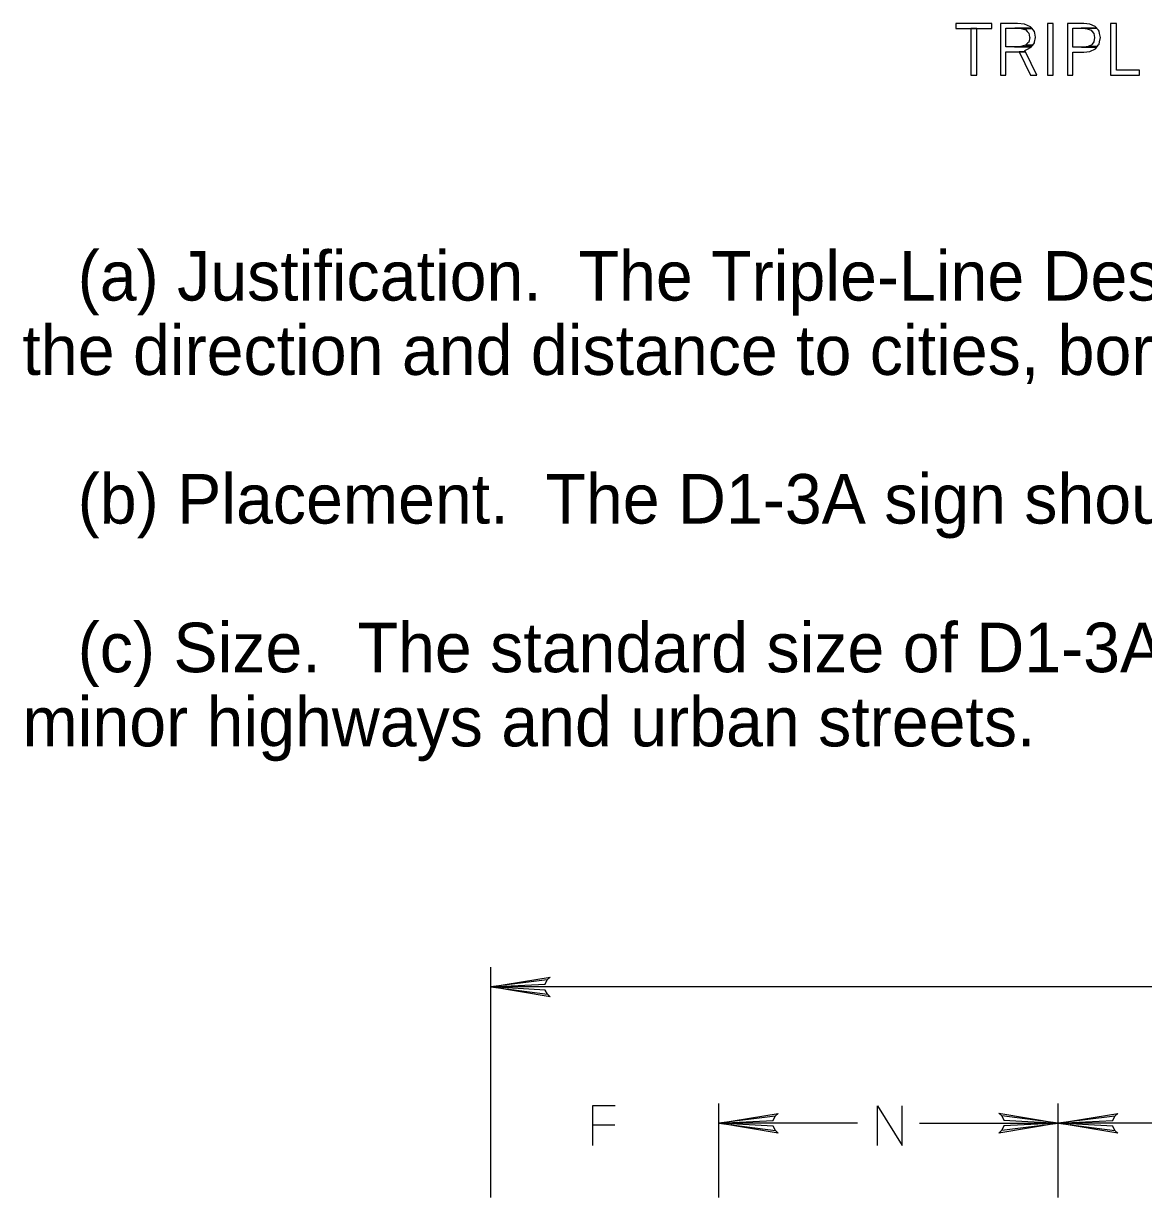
# Model space of a CAD drawing. Extents: x 0.011 to 0.188, y 0.004 to 0.261.
# Drawn here: x 0.0252 to 0.0822, y 0.1928 to 0.2525 of the extents above; entities that cross this region are included whole.
import ezdxf

# ---------------------------------------------------------------- set-up
doc = ezdxf.new("R2010")
doc.units = 0
doc.layers.add('1', color=7, linetype='Continuous')
doc.layers.add('3', color=7, linetype='Continuous')

# ---------------------------------------------------------------- blocks, each defined once
blk = doc.blocks.new('RARROW')
at = {"layer": '3'}
for p, q in [((-2.156, 0.285), (-2.2665, 0.384625)), ((-2.2665, 0.384625), (0, 0)), ((0, 0), (-2.2665, -0.379125)), ((-2.156, 0.285), (-2.075625, 0.12075)), ((0, 0), (-2.156, 0.285)), ((-2.14975, -0.2705), (0, 0)), ((-2.075625, 0.12075), (0, 0)), ((0, 0), (-2.074, -0.108)), ((-2.2665, -0.379125), (-2.14975, -0.2705)), ((-2.074, -0.108), (-2.14975, -0.2705))]:
    blk.add_line(p, q, dxfattribs=at)

msp = doc.modelspace()

# ---------------------------------------------------------------- linework, layer by layer
at = {"layer": '1'}
for points in [[(0.072644, 0.252474), (0.072644, 0.252222), (0.074473, 0.252222), (0.074473, 0.252474)], [(0.073409, 0.252222), (0.073409, 0.249848), (0.073707, 0.249848), (0.073707, 0.252222)], [(0.074907, 0.251038), (0.074907, 0.249848), (0.075193, 0.249848), (0.075193, 0.251038), (0.076181, 0.251038), (0.076147, 0.251107), (0.07626, 0.251146), (0.076466, 0.251262), (0.076481, 0.251282), (0.075193, 0.251282), (0.075193, 0.251286), (0.075193, 0.251303), (0.075193, 0.251377), (0.075193, 0.251483), (0.075193, 0.251531), (0.075193, 0.251755), (0.075193, 0.251778), (0.075193, 0.251988), (0.075193, 0.252073), (0.075193, 0.252149), (0.075193, 0.252214), (0.075193, 0.252227), (0.075193, 0.252229), (0.076505, 0.252229), (0.076439, 0.252309), (0.076135, 0.25244), (0.075787, 0.25247), (0.075645, 0.252474), (0.074907, 0.252474), (0.074907, 0.25247), (0.074907, 0.25244), (0.074907, 0.252309), (0.074907, 0.252229), (0.074907, 0.252227), (0.074907, 0.252214), (0.074907, 0.252149), (0.074907, 0.252073), (0.074907, 0.251988), (0.074907, 0.251778), (0.074907, 0.251755), (0.074907, 0.251531), (0.074907, 0.251483), (0.074907, 0.251377), (0.074907, 0.251303), (0.074907, 0.251286), (0.074907, 0.251282), (0.074907, 0.251262), (0.074907, 0.251146), (0.074907, 0.251107)], [(0.075763, 0.252227), (0.07597, 0.252214), (0.076518, 0.252214), (0.076508, 0.252227), (0.076507, 0.252227), (0.076505, 0.252229), (0.075642, 0.252229)], [(0.0763, 0.251483), (0.07619, 0.251377), (0.076554, 0.251377), (0.076636, 0.251483), (0.076645, 0.251531), (0.076689, 0.251755), (0.076693, 0.251778), (0.076653, 0.251988), (0.076636, 0.252073), (0.076572, 0.252149), (0.076518, 0.252214), (0.07597, 0.252214), (0.076198, 0.252149), (0.076272, 0.252073), (0.076354, 0.251988), (0.076395, 0.251778), (0.076399, 0.251755), (0.07635, 0.251531)], [(0.077297, 0.252474), (0.077297, 0.249848), (0.077591, 0.249848), (0.077591, 0.252474)], [(0.078314, 0.251021), (0.078314, 0.249848), (0.078596, 0.249848), (0.078596, 0.251021), (0.079158, 0.251021), (0.079458, 0.251057), (0.079742, 0.251189), (0.079805, 0.251267), (0.078598, 0.251267), (0.078598, 0.251268), (0.078598, 0.251297), (0.078598, 0.251391), (0.078598, 0.251427), (0.078598, 0.251545), (0.078598, 0.251759), (0.078598, 0.25176), (0.078598, 0.251969), (0.078598, 0.252078), (0.078598, 0.252135), (0.078598, 0.252209), (0.078598, 0.252227), (0.078598, 0.252228), (0.079814, 0.252228), (0.079736, 0.252322), (0.079454, 0.252443), (0.07916, 0.252472), (0.079075, 0.252474), (0.078314, 0.252474), (0.078314, 0.252472), (0.078314, 0.252443), (0.078314, 0.252322), (0.078314, 0.252228), (0.078314, 0.252227), (0.078314, 0.252209), (0.078314, 0.252135), (0.078314, 0.252078), (0.078314, 0.251969), (0.078314, 0.25176), (0.078314, 0.251759), (0.078314, 0.251545), (0.078314, 0.251427), (0.078314, 0.251391), (0.078314, 0.251297), (0.078314, 0.251268), (0.078314, 0.251267), (0.078314, 0.251189), (0.078314, 0.251057)], [(0.079558, 0.251391), (0.079376, 0.251297), (0.079828, 0.251297), (0.079904, 0.251391), (0.079933, 0.251427), (0.079955, 0.251545), (0.079994, 0.251759), (0.079994, 0.25176), (0.079957, 0.251969), (0.079938, 0.252078), (0.07989, 0.252135), (0.079829, 0.252209), (0.079815, 0.252227), (0.079814, 0.252228), (0.07902, 0.252228), (0.079118, 0.252227), (0.079323, 0.252209), (0.079518, 0.252135), (0.079566, 0.252078), (0.079659, 0.251969), (0.079697, 0.25176), (0.079696, 0.251759), (0.079665, 0.251545), (0.079583, 0.251427)], [(0.080515, 0.2501), (0.080515, 0.249848), (0.081985, 0.249848), (0.081985, 0.2501), (0.080811, 0.2501), (0.080811, 0.252474), (0.080515, 0.252474)], [(0.075726, 0.251286), (0.075631, 0.251282), (0.076481, 0.251282), (0.076484, 0.251286), (0.076497, 0.251303), (0.076554, 0.251377), (0.07619, 0.251377), (0.075951, 0.251303)], [(0.075868, 0.251038), (0.076444, 0.249848), (0.076764, 0.249848), (0.076181, 0.251038)], [(0.079145, 0.251268), (0.079041, 0.251267), (0.079805, 0.251267), (0.079805, 0.251268), (0.079828, 0.251297), (0.079375, 0.251297)]]:
    msp.add_lwpolyline(points, close=True, dxfattribs=at)
at = {"layer": '3'}
for p, q in [((0.049001, 0.197558), (0.049001, 0.204488)), ((0.107815, 0.20348), (0.049001, 0.20348)), ((0.049001, 0.19277), (0.049001, 0.197558)), ((0.060593, 0.19277), (0.060593, 0.197558)), ((0.060593, 0.19655), (0.063617, 0.197051)), ((0.063617, 0.197051), (0.063462, 0.196907)), ((0.074979, 0.196927), (0.074831, 0.197058)), ((0.074831, 0.197058), (0.077855, 0.19655)), ((0.077855, 0.19277), (0.077855, 0.197558)), ((0.077855, 0.19655), (0.080879, 0.197051)), ((0.080879, 0.197051), (0.080724, 0.196907)), ((0.063462, 0.196907), (0.060593, 0.19655)), ((0.060593, 0.19655), (0.063361, 0.196693)), ((0.067649, 0.19655), (0.060593, 0.19655)), ((0.063363, 0.196391), (0.060593, 0.19655)), ((0.060593, 0.19655), (0.06347, 0.196174)), ((0.063617, 0.196043), (0.060593, 0.19655)), ((0.063361, 0.196693), (0.063462, 0.196907)), ((0.070799, 0.19655), (0.077855, 0.19655)), ((0.077855, 0.19655), (0.074831, 0.19605)), ((0.074979, 0.196927), (0.075086, 0.19671)), ((0.077855, 0.19655), (0.074979, 0.196927)), ((0.074987, 0.196193), (0.077855, 0.19655)), ((0.075086, 0.19671), (0.077855, 0.19655)), ((0.077855, 0.19655), (0.075088, 0.196408)), ((0.080724, 0.196907), (0.077855, 0.19655)), ((0.077855, 0.19655), (0.080623, 0.196693)), ((0.106457, 0.19655), (0.077855, 0.19655)), ((0.080625, 0.196391), (0.077855, 0.19655)), ((0.077855, 0.19655), (0.080732, 0.196174)), ((0.080879, 0.196043), (0.077855, 0.19655)), ((0.080623, 0.196693), (0.080724, 0.196907)), ((0.06347, 0.196174), (0.063363, 0.196391)), ((0.06347, 0.196174), (0.063617, 0.196043)), ((0.074831, 0.19605), (0.074987, 0.196193)), ((0.075088, 0.196408), (0.074987, 0.196193)), ((0.080732, 0.196174), (0.080625, 0.196391)), ((0.080732, 0.196174), (0.080879, 0.196043))]:
    msp.add_line(p, q, dxfattribs=at)
for points in [[(0.055326, 0.197433), (0.054167, 0.197433), (0.054167, 0.195416)], [(0.068657, 0.195416), (0.068657, 0.197433), (0.069912, 0.195416), (0.069912, 0.197433)], [(0.054167, 0.196448), (0.054167, 0.196448)], [(0.05531, 0.196448), (0.054167, 0.196448)]]:
    msp.add_lwpolyline(points, dxfattribs=at)

# ---------------------------------------------------------------- block references
at = {"layer": '3', "xscale": 0.0013342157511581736, "yscale": 0.0013198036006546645, "rotation": 180}
msp.add_blockref('RARROW', (0.049001, 0.20348), dxfattribs=at)

# ---------------------------------------------------------------- texts
at = {"layer": '3'}
for s, height, p in [('   (a) Justification.  The Triple-Line Destination Mileage Sign (D1-3A) shall be authorized for use to indicate', 0.002519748, (0.025187, 0.238382)), ('the direction and distance to cities, boroughs and villages, etc.', 0.00251975, (0.025187, 0.234602)), ('   (b) Placement.  The D1-3A sign should generally be placed in advance of an intersection.', 0.00251975, (0.025187, 0.227042)), ('   (c) Size.  The standard size of D1-3A sign shall be 72" x 36".  The 48" x 24" size may be used on', 0.00251975, (0.025187, 0.219482)), ('minor highways and urban streets.', 0.00251975, (0.025187, 0.215713))]:
    msp.add_text(s, height=height, dxfattribs=at).set_placement(p)

doc.saveas('drawing.dxf')
